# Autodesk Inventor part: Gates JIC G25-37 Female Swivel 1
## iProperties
Author: Larry Caldwell
Shininess: 64.0
Angle Display Precision: 2
Document Length Units: 11272
Document Angle Units: 11286
Document Time Units: 11279
Document Mass Units: 11290
Document Length Units Precision: 3
Document Angle Units Precision: 2
Compacted: True
PropertySet Name: _Private Model Information
Created: 2001-11
Part Number: Gates JIC G25-37 Female Swivel 1
Description: Gates G25 JIC-37 Female Swivel 3/4-16 UNF 08-08
Document SubType Name: Modeling
Designer: Larry Caldwell
Control State: 0
Master: False
Checked Out: False
PropertySet Name: Design Tracking Control
Density: 0.0
Volumn: 0.0
Area: 0.0
PropertySet Name: Model Information
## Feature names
1. Coupling [Revolution]
2. StemHex [Extrusion]
3. StemHex Cut [Revolution]
4. Extrusion4
5. Revolution5
6. Revolution12
7. Fillet2
8. Circular Pattern2
